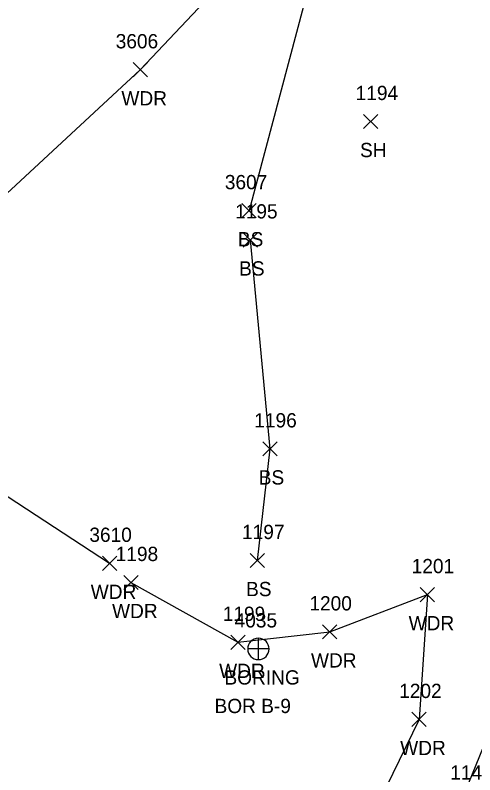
# Model space of a CAD drawing. Extents: x 1634209 to 1639641, y 608564 to 612258.
# Drawn here: x 1639356.8 to 1639421.2, y 611953 to 612059.5 of the extents above; entities that cross this region are included whole.
import ezdxf

# ---------------------------------------------------------------- set-up
doc = ezdxf.new("R2010")
doc.units = 0
for name, color, linetype in [('G_A', 7, 'Continuous'), ('G_C', 7, 'Continuous'), ('G_I', 7, 'Continuous'), ('GA_P', 7, 'Continuous'), ('L_A', 7, 'Continuous'), ('L_I', 7, 'Continuous'), ('L_TIC', 7, 'Continuous'), ('LAWA', 7, 'Continuous'), ('LELB', 7, 'Continuous')]:
    doc.layers.add(name, color=color, linetype=linetype)

msp = doc.modelspace()

# ---------------------------------------------------------------- linework, layer by layer
at = {"layer": 'GA_P'}
for p, q in [((1639390.88, 611970.63), (1639390.88, 611972.13)), ((1639390.88, 611970.63), (1639389.38, 611970.63)), ((1639392.38, 611970.63), (1639390.88, 611970.63)), ((1639390.88, 611969.13), (1639390.88, 611970.63))]:
    msp.add_line(p, q, dxfattribs=at)
for start, end in [(90, 180), (0, 90), (180, 270), (270, 0)]:
    msp.add_arc((1639390.88, 611970.63), 1.5, start, end, dxfattribs=at)
at = {"layer": 'L_TIC'}
for points in [[(1639373.32, 612050.81), (1639375.32, 612052.81)], [(1639375.32, 612050.81), (1639373.32, 612052.81)], [(1639405.62, 612043.56), (1639407.62, 612045.56)], [(1639407.62, 612043.56), (1639405.62, 612045.56)], [(1639388.56, 612031.06), (1639390.56, 612033.06)], [(1639390.56, 612031.06), (1639388.56, 612033.06)], [(1639388.73, 612026.96), (1639390.73, 612028.96)], [(1639390.73, 612026.96), (1639388.73, 612028.96)], [(1639391.48, 611997.67), (1639393.48, 611999.67)], [(1639393.48, 611997.67), (1639391.48, 611999.67)], [(1639369.02, 611981.63), (1639371.02, 611983.63)], [(1639371.02, 611981.63), (1639369.02, 611983.63)], [(1639389.71, 611982.02), (1639391.71, 611984.02)], [(1639391.71, 611982.02), (1639389.71, 611984.02)], [(1639372.01, 611978.94), (1639374.01, 611980.94)], [(1639374.01, 611978.94), (1639372.01, 611980.94)], [(1639413.55, 611977.24), (1639415.55, 611979.24)], [(1639415.55, 611977.24), (1639413.55, 611979.24)], [(1639399.87, 611972.02), (1639401.87, 611974.02)], [(1639401.87, 611972.02), (1639399.87, 611974.02)], [(1639387.01, 611970.55), (1639389.01, 611972.55)], [(1639389.01, 611970.55), (1639387.01, 611972.55)], [(1639412.38, 611959.74), (1639414.38, 611961.74)], [(1639414.38, 611959.74), (1639412.38, 611961.74)]]:
    msp.add_lwpolyline(points, dxfattribs=at)
at = {"layer": 'LAWA'}
for points in [[(1639462.56, 612220.23), (1639462.33, 612196), (1639459.44, 612165.18), (1639453.07, 612136.65), (1639437.54, 612092.46), (1639402.84, 612082.03), (1639374.32, 612051.81), (1639347.85, 612027.27), (1639335.09, 612005.49), (1639370.02, 611982.63)], [(1639373.01, 611979.94), (1639388.01, 611971.55), (1639400.87, 611973.02), (1639414.55, 611978.24), (1639413.38, 611960.74), (1639401.36, 611936), (1639389.58, 611917.71), (1639376.62, 611922.64), (1639376.82, 611940.14), (1639365.3, 611945.9)]]:
    msp.add_lwpolyline(points, dxfattribs=at)
at = {"layer": 'LELB'}
for points in [[(1639515.85, 612224.44), (1639477.4, 612210.66), (1639462.33, 612196), (1639435.98, 612184.15), (1639403.66, 612152.3), (1639406.78, 612109.36), (1639402.84, 612082.03), (1639389.56, 612032.06)], [(1639389.73, 612027.96), (1639392.48, 611998.67), (1639390.71, 611983.02)], [(1639383.1, 611838.36), (1639397.42, 611885.01), (1639407.84, 611916.5), (1639419.32, 611949.32), (1639430.83, 611977.53), (1639440.14, 611998.75)]]:
    msp.add_lwpolyline(points, dxfattribs=at)

# ---------------------------------------------------------------- texts
at = {"layer": 'G_A'}
msp.add_text('BORING', height=2, dxfattribs=at).set_placement((1639386.12, 611965.63))
at = {"layer": 'G_C'}
msp.add_text('BOR B-9', height=2, dxfattribs=at).set_placement((1639384.73, 611961.63))
at = {"layer": 'G_I'}
msp.add_text('4035', height=2, dxfattribs=at).set_placement((1639387.54, 611973.63))
at = {"layer": 'L_A'}
for s, p in [('WDR', (1639371.68, 612046.81)), ('SH', (1639405.11, 612039.56)), ('BS', (1639388, 612027.06)), ('BS', (1639388.17, 612022.96)), ('BS', (1639390.92, 611993.67)), ('WDR', (1639367.38, 611977.63)), ('BS', (1639389.15, 611978.02)), ('WDR', (1639370.37, 611974.94)), ('WDR', (1639411.92, 611973.24)), ('WDR', (1639398.24, 611968.02)), ('WDR', (1639385.37, 611966.55)), ('WDR', (1639410.74, 611955.74))]:
    msp.add_text(s, height=2, dxfattribs=at).set_placement(p)
at = {"layer": 'L_I'}
for s, p in [('3606', (1639370.88, 612054.81)), ('1194', (1639404.5, 612047.56)), ('3607', (1639386.17, 612035.06)), ('1195', (1639387.61, 612030.96)), ('1196', (1639390.3, 612001.67)), ('3610', (1639367.19, 611985.63)), ('1197', (1639388.58, 611986.02)), ('1198', (1639370.88, 611982.94)), ('1201', (1639412.35, 611981.24)), ('1200', (1639398.02, 611976.02)), ('1199', (1639385.88, 611974.55)), ('1202', (1639410.6, 611963.74)), ('1141', (1639417.76, 611952.32))]:
    msp.add_text(s, height=2, dxfattribs=at).set_placement(p)

doc.saveas('drawing.dxf')
